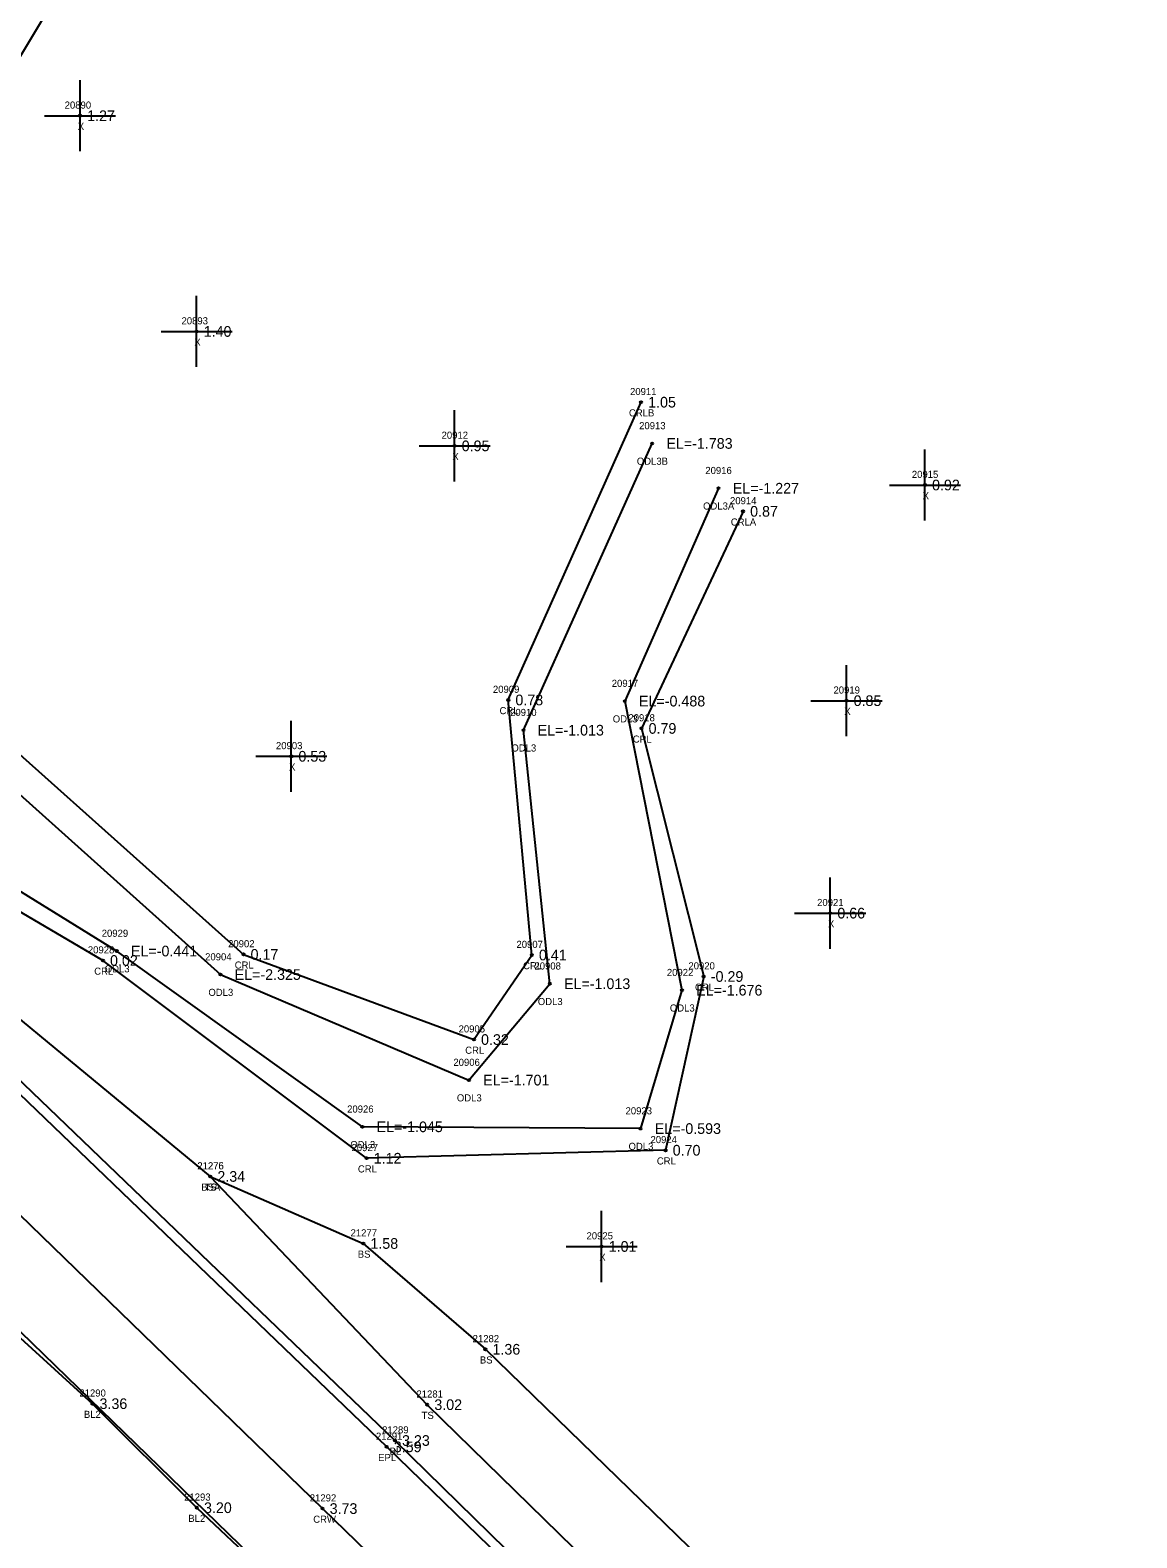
# Model space of a CAD drawing. Extents: x 2608745 to 2610333, y 641917 to 643463.
# Drawn here: x 2609730.2 to 2609885.8, y 642446.2 to 642658.2 of the extents above; entities that cross this region are included whole.
import ezdxf

# ---------------------------------------------------------------- set-up
doc = ezdxf.new("R2010")
doc.units = 0
for name, color, linetype in [('RD_DTM_BkLn1', 7, 'Continuous'), ('RD_DTM_BkLn2', 7, 'Continuous'), ('RD_DTM_BkLn_txCode', 7, 'Continuous'), ('RD_EX_H2O', 7, 'Continuous'), ('RD_EX_H2O_txCode', 7, 'Continuous'), ('RD_EX_Misc', 7, 'Continuous'), ('RD_EX_Misc_txCode', 7, 'Continuous'), ('RD_EX_Road', 7, 'Continuous'), ('RD_EX_Road_txCode', 7, 'Continuous'), ('RD_EX_TX_H2O_ELEV', 7, 'Continuous'), ('RD_EX_TX_Misc_ELEV', 7, 'Continuous'), ('RD_EX_TX_Road_ELEV', 7, 'Continuous'), ('RD_HC_Survey_ELEV', 7, 'Continuous'), ('RD_HC_Survey_txCode', 7, 'Continuous'), ('RD_SMD_Locator', 7, 'Continuous')]:
    doc.layers.add(name, color=color, linetype=linetype)

msp = doc.modelspace()

# ---------------------------------------------------------------- linework, layer by layer
at = {"layer": 'RD_DTM_BkLn1'}
for points in [[(2609568.4, 642647.43), (2609618.95, 642597.92), (2609693.89, 642525.38), (2609771.33, 642450.27), (2609850.26, 642373.69), (2609929.54, 642297.24), (2610000.01, 642230.49), (2610078.71, 642154.75), (2610156.09, 642080.44), (2610235.53, 642002.94), (2610263.59, 641975.77)], [(2609627.58, 642607.09), (2609630.23, 642605.37), (2609646.31, 642589.45), (2609703.16, 642535.02), (2609781.51, 642459.84), (2609859.44, 642383.51), (2609938.95, 642307.03), (2610008.76, 642239.49), (2610086.74, 642162.99), (2610105.31, 642145.89), (2610105.31, 642145.89), (2610140.26, 642113.1), (2610153.89, 642100.28), (2610164.72, 642089.82), (2610189.2, 642065.46)], [(2609638.64, 642561.68), (2609646.49, 642552.99), (2609655.41, 642544.68), (2609682.3, 642518.46), (2609696.97, 642504.35), (2609720.79, 642481.57), (2609738.97, 642465.02), (2609753.66, 642450.39), (2609762.69, 642441.83), (2609780.95, 642423.34), (2609796.2, 642407.99), (2609840.83, 642364.55), (2609897.27, 642310.29), (2609920.64, 642289.07), (2609961.88, 642250.25), (2609968.31, 642243.41), (2609978.92, 642233.98)]]:
    msp.add_lwpolyline(points, dxfattribs=at)
at = {"layer": 'RD_DTM_BkLn2'}
for points in [[(2609582.66, 642657.54), (2609585.75, 642657.34), (2609622.53, 642623.2), (2609632.13, 642611.9), (2609647.4, 642591.36), (2609682.93, 642558.52), (2609706.14, 642537.77), (2609755.54, 642496.98), (2609786.05, 642464.88), (2609864.24, 642388.44), (2609941.53, 642310.67), (2610012.94, 642244.46), (2610082.83, 642179.18), (2610093.52, 642170.29)], [(2609755.54, 642496.98), (2609777.06, 642487.55), (2609794.23, 642472.67), (2609873.31, 642395.79), (2609950.73, 642318.92), (2610015.83, 642247.73), (2610085.46, 642180.03), (2610093.52, 642170.29)]]:
    msp.add_lwpolyline(points, dxfattribs=at)
at = {"layer": 'RD_EX_H2O'}
for points in [[(2609943.79, 642976.05), (2609869.55, 642907.14), (2609797.73, 642847.7), (2609725.24, 642780.75), (2609667.97, 642714.2), (2609673.28, 642700.22), (2609713.56, 642689.91), (2609733.33, 642661.98), (2609719.28, 642638.68), (2609663.61, 642631.91), (2609659.09, 642626.02), (2609711.84, 642571.44), (2609760.21, 642528.21), (2609792.62, 642516.23), (2609800.76, 642528.12), (2609797.45, 642563.99), (2609816.12, 642605.87)], [(2609662.06, 642711.74), (2609667.71, 642698.47), (2609710.28, 642682.9), (2609727.91, 642663.26), (2609716.99, 642643.97), (2609660.46, 642637.14), (2609654.51, 642626.15), (2609709.09, 642568.34), (2609756.97, 642525.37), (2609791.92, 642510.53), (2609803.29, 642524.08), (2609799.58, 642559.74), (2609817.68, 642600.07)], [(2609827.02, 642593.77), (2609813.83, 642563.83), (2609821.87, 642523.17), (2609816.05, 642503.71), (2609776.93, 642503.96), (2609742.39, 642528.68), (2609685.39, 642563.92), (2609653.36, 642600.13), (2609643.82, 642618.08), (2609649.2, 642642.17), (2609682.55, 642662.2), (2609681.94, 642669.7), (2609650.34, 642688.25), (2609625.49, 642693.15)], [(2609830.46, 642590.52), (2609816.18, 642559.99), (2609824.93, 642525.1), (2609819.57, 642500.66), (2609777.53, 642499.54), (2609740.45, 642527.35), (2609685.03, 642559.92), (2609648.92, 642598.17), (2609639.51, 642613.04), (2609644.31, 642644.72), (2609677.66, 642665.76), (2609646.17, 642685.39), (2609611.73, 642684.8), (2609586.16, 642666.36), (2609575.62, 642664.58), (2609550.15, 642638.19)]]:
    msp.add_lwpolyline(points, dxfattribs=at)
at = {"layer": 'RD_EX_Misc'}
for p, q in [((2609737.23, 642641.16), (2609737.23, 642651.16)), ((2609732.23, 642646.16), (2609742.23, 642646.16)), ((2609753.62, 642610.82), (2609753.62, 642620.82)), ((2609748.62, 642615.82), (2609758.62, 642615.82)), ((2609789.9, 642594.73), (2609789.9, 642604.73)), ((2609784.9, 642599.73), (2609794.9, 642599.73)), ((2609856.04, 642589.22), (2609856.04, 642599.22)), ((2609851.04, 642594.22), (2609861.04, 642594.22)), ((2609845.01, 642558.89), (2609845.01, 642568.89)), ((2609840.01, 642563.89), (2609850.01, 642563.89)), ((2609766.94, 642551.07), (2609766.94, 642561.07)), ((2609761.94, 642556.07), (2609771.94, 642556.07)), ((2609842.72, 642529.01), (2609842.72, 642539.01)), ((2609837.72, 642534.01), (2609847.72, 642534.01)), ((2609810.57, 642482.13), (2609810.57, 642492.13)), ((2609805.57, 642487.13), (2609815.57, 642487.13))]:
    msp.add_line(p, q, dxfattribs=at)
at = {"layer": 'RD_EX_Road'}
for points in [[(2609576.61, 642656.06), (2609590.88, 642642.24), (2609605.19, 642628.78), (2609627.58, 642607.09), (2609646.03, 642589.11), (2609702.18, 642534.04), (2609780.35, 642458.95), (2609858.79, 642382.83), (2609938.32, 642306.42), (2610008.62, 642239.32), (2610086.3, 642162.54), (2610164.18, 642089.49), (2610189.2, 642065.46), (2610214.78, 642040.19), (2610225.86, 642030.16), (2610226.32, 642028.39), (2610235.43, 642019.75), (2610260.23, 641995.63), (2610272.39, 641983.25)], [(2609560.29, 642639.04), (2609610.49, 642589.69), (2609620.39, 642580.29), (2609634.49, 642566.49), (2609647.6, 642554.19), (2609656.49, 642545.43), (2609683.33, 642519.48), (2609697.84, 642505.38), (2609722.29, 642481.47), (2609722.29, 642481.47), (2609722.29, 642481.47), (2609762.93, 642442.03), (2609781.47, 642423.77), (2609797.04, 642408.62), (2609841.8, 642365.54), (2609898.22, 642311.07)]]:
    msp.add_lwpolyline(points, dxfattribs=at)
at = {"layer": 'RD_SMD_Locator'}
for centre in [(2609737.23, 642646.16), (2609753.62, 642615.82), (2609816.12, 642605.87), (2609789.9, 642599.73), (2609817.68, 642600.07), (2609856.04, 642594.22), (2609827.02, 642593.77), (2609830.46, 642590.52), (2609797.45, 642563.99), (2609813.83, 642563.83), (2609845.01, 642563.89), (2609799.58, 642559.74), (2609816.18, 642559.99), (2609766.94, 642556.07), (2609842.72, 642534.01), (2609742.39, 642528.68), (2609740.45, 642527.35), (2609760.21, 642528.21), (2609800.76, 642528.12), (2609756.97, 642525.37), (2609824.93, 642525.1), (2609803.29, 642524.08), (2609821.87, 642523.17), (2609792.62, 642516.23), (2609791.92, 642510.53), (2609776.93, 642503.96), (2609816.05, 642503.71), (2609777.53, 642499.54), (2609819.57, 642500.66), (2609755.54, 642496.98), (2609755.54, 642496.98), (2609777.06, 642487.55), (2609810.57, 642487.13), (2609794.23, 642472.67), (2609738.97, 642465.02), (2609786.05, 642464.88), (2609780.35, 642458.95), (2609781.51, 642459.84), (2609753.66, 642450.39), (2609771.33, 642450.27)]:
    msp.add_circle(centre, 0.15, dxfattribs=at)

# ---------------------------------------------------------------- texts
at = {"layer": 'RD_DTM_BkLn_txCode'}
for s, p in [('21276', (2609753.72, 642497.98)), ('21275', (2609753.74, 642497.98)), ('BSA', (2609754.27, 642494.98)), ('TS', (2609754.74, 642494.98)), ('21277', (2609775.27, 642488.55)), ('BS', (2609776.28, 642485.55)), ('21282', (2609792.44, 642473.67)), ('BS', (2609793.45, 642470.67)), ('21290', (2609737.14, 642466.02)), ('21281', (2609784.54, 642465.88)), ('BL2', (2609737.77, 642463.02)), ('TS', (2609785.26, 642462.88)), ('21289', (2609779.71, 642460.84)), ('BL', (2609780.75, 642457.84)), ('21293', (2609751.87, 642451.39)), ('BL2', (2609752.46, 642448.39))]:
    msp.add_text(s, height=1, dxfattribs=at).set_placement(p)
at = {"layer": 'RD_EX_H2O_txCode'}
for s, p in [('20911', (2609814.57, 642606.87)), ('CRLB', (2609814.42, 642603.87)), ('20913', (2609815.85, 642602.07)), ('ODL3B', (2609815.52, 642597.07)), ('20916', (2609825.16, 642595.77)), ('20914', (2609828.63, 642591.52)), ('ODL3A', (2609824.84, 642590.77)), ('CRLA', (2609828.74, 642588.52)), ('20917', (2609812, 642565.83)), ('20909', (2609795.29, 642564.99)), ('CRL', (2609796.22, 642561.99)), ('20910', (2609797.71, 642561.74)), ('ODL3', (2609812.14, 642560.83)), ('20918', (2609814.34, 642560.99)), ('CRL', (2609814.95, 642557.99)), ('ODL3', (2609797.89, 642556.74)), ('20929', (2609740.28, 642530.68)), ('20928', (2609738.33, 642528.35)), ('20902', (2609758.05, 642529.21)), ('20907', (2609798.6, 642529.12)), ('ODL3', (2609740.7, 642525.68)), ('20904', (2609754.82, 642527.37)), ('CRL', (2609758.98, 642526.21)), ('CRL', (2609799.53, 642526.12)), ('20908', (2609801.13, 642526.08)), ('20920', (2609822.78, 642526.1)), ('CRL', (2609739.22, 642525.35)), ('20922', (2609819.75, 642525.17)), ('ODL3', (2609755.28, 642522.37)), ('CRL', (2609823.7, 642523.1)), ('ODL3', (2609801.6, 642521.08)), ('ODL3', (2609820.17, 642520.17)), ('20905', (2609790.46, 642517.23)), ('CRL', (2609791.39, 642514.23)), ('20906', (2609789.73, 642512.53)), ('ODL3', (2609790.22, 642507.53)), ('20926', (2609774.79, 642505.96)), ('20923', (2609813.94, 642505.71)), ('ODL3', (2609775.24, 642500.96)), ('20927', (2609775.41, 642500.54)), ('ODL3', (2609814.36, 642500.71)), ('20924', (2609817.45, 642501.66)), ('CRL', (2609818.34, 642498.66)), ('CRL', (2609776.3, 642497.54))]:
    msp.add_text(s, height=1, dxfattribs=at).set_placement(p)
at = {"layer": 'RD_EX_Misc_txCode'}
for s, p in [('20890', (2609735.07, 642647.16)), ('X', (2609736.91, 642644.16)), ('20893', (2609751.5, 642616.82)), ('X', (2609753.3, 642613.82)), ('20912', (2609788.07, 642600.73)), ('X', (2609789.59, 642597.73)), ('20915', (2609854.2, 642595.22)), ('X', (2609855.72, 642592.22)), ('20919', (2609843.18, 642564.89)), ('X', (2609844.7, 642561.89)), ('20903', (2609764.78, 642557.07)), ('X', (2609766.62, 642554.07)), ('20921', (2609840.88, 642535.01)), ('X', (2609842.4, 642532.01)), ('20925', (2609808.45, 642488.13)), ('X', (2609810.25, 642485.13))]:
    msp.add_text(s, height=1, dxfattribs=at).set_placement(p)
at = {"layer": 'RD_EX_Road_txCode'}
for s, p in [('21291', (2609778.84, 642459.95)), ('EPL', (2609779.15, 642456.95))]:
    msp.add_text(s, height=1, dxfattribs=at).set_placement(p)
at = {"layer": 'RD_EX_TX_H2O_ELEV'}
for s, p in [('1.05', (2609817.12, 642605.12)), ('EL=-1.783', (2609819.68, 642599.32)), ('EL=-1.227', (2609829.02, 642593.02)), ('0.87', (2609831.46, 642589.77)), ('0.78', (2609798.45, 642563.24)), ('EL=-0.488', (2609815.83, 642563.08)), ('EL=-1.013', (2609801.58, 642558.99)), ('0.79', (2609817.18, 642559.24)), ('EL=-0.441', (2609744.39, 642527.93)), ('0.17', (2609761.21, 642527.46)), ('0.41', (2609801.76, 642527.37)), ('0.02', (2609741.45, 642526.6)), ('EL=-2.325', (2609758.97, 642524.62)), ('EL=-1.013', (2609805.29, 642523.33)), ('-0.29', (2609825.93, 642524.35)), ('EL=-1.676', (2609823.87, 642522.42)), ('0.32', (2609793.62, 642515.48)), ('EL=-1.701', (2609793.92, 642509.78)), ('EL=-1.045', (2609778.93, 642503.21)), ('EL=-0.593', (2609818.05, 642502.96)), ('0.70', (2609820.57, 642499.91)), ('1.12', (2609778.53, 642498.79))]:
    msp.add_text(s, height=1.5, dxfattribs=at).set_placement(p)
at = {"layer": 'RD_EX_TX_Misc_ELEV'}
for s, p in [('1.27', (2609738.23, 642645.41)), ('1.40', (2609754.62, 642615.07)), ('0.95', (2609790.9, 642598.98)), ('0.92', (2609857.04, 642593.47)), ('0.85', (2609846.01, 642563.14)), ('0.53', (2609767.94, 642555.32)), ('0.66', (2609843.72, 642533.26)), ('2.34', (2609756.54, 642496.23)), ('2.34', (2609756.54, 642496.23)), ('1.58', (2609778.06, 642486.8)), ('1.01', (2609811.57, 642486.38)), ('1.36', (2609795.23, 642471.92)), ('3.36', (2609739.97, 642464.27)), ('3.02', (2609787.05, 642464.13)), ('3.23', (2609782.51, 642459.09)), ('3.20', (2609754.66, 642449.64))]:
    msp.add_text(s, height=1.5, dxfattribs=at).set_placement(p)
at = {"layer": 'RD_EX_TX_Road_ELEV'}
msp.add_text('3.59', height=1.5, dxfattribs=at).set_placement((2609781.35, 642458.2))
at = {"layer": 'RD_HC_Survey_ELEV'}
msp.add_text('3.73', height=1.5, dxfattribs=at).set_placement((2609772.33, 642449.52))
at = {"layer": 'RD_HC_Survey_txCode'}
for s, p in [('21292', (2609769.54, 642451.27)), ('CRW', (2609770.02, 642448.27))]:
    msp.add_text(s, height=1, dxfattribs=at).set_placement(p)

doc.saveas('drawing.dxf')
